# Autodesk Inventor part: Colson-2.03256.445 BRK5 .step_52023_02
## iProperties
Created: 2010-10
Part Number: Colson-2.03256.445 BRK5 .step_52023_02
Document SubType Name: Modeling
Designer: Administrator
Density: 7.85 g/cm^3
Material: Steel
Mass: 6.19676 g
Surface Area: 8.22046 cm^2
Volume: 0.789396 cm^3
Author: Administrator
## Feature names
1. Base1
